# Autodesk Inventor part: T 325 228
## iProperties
Company: Mayer & Müller AG Schaltgeräte
Created: 2006-04
Part Number: T 325 228
Material: Standard
Document SubType Name: Modeling
Designer: I.Baliuc
Description: Schutzabdeckung, links
Density: 1 g/cm^3
Author: T.Messerschmitt
Revision Number: 325228
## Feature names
1. Extrusion2
2. Rundung3 [Fillet]
3. Wandstärke1
4. Extrusion3
5. Bohrung_Ø7 [Hole]
